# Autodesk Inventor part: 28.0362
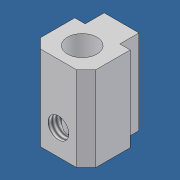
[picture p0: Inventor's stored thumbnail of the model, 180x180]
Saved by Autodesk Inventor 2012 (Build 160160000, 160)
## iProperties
Created: 2011-09
Part Number: 28.0362
Document SubType Name: Modeling
Designer: Administrator
Density: 2.71 g/cm^3
Material: Aluminum-6061
Mass: 6.60718 g
Surface Area: 18.2138 cm^2
Volume: 2.43808 cm^3
Description: CLAMP BLOCK
Vendor: S
Author: Administrator
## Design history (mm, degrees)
sketch "Sketch1"
  geometry: L1 (-4.1, 9.295)-(4.1, 9.295); L2 (-4.1, 9.295)-(-4.1, 4.795); L3 (4.1, 9.295)-(4.1, 4.795); L4 (4.1, 4.795)-(6.55, 4.795); L5 (6.55, 4.795)-(6.55, -5.615); L6 (6.55, -5.615)-(-6.55, -5.615); L7 (-6.55, -5.615)-(-6.55, 4.795); L8 (-6.55, 4.795)-(-4.1, 4.795); C1 r 3.485 at (0, 0); 2 further points
  constraints: 16 end point, 4 parallel, 2 collinear, 2 perpendicular, 1 centre point, 1 coincident, 1 horizontal, 1 horizontal alignment, 1 midpoint, 1 vertical alignment
  dimensions: "d0" = 6.97 diameter of C1; "d1" = 8.2 distance of L1.start L1.end; "d2" = 13.1 distance between parallel lines of L5 L7; "d3" = 14.91 distance between parallel lines of L6 L1; "d4" = 4.5 distance of L1.start L2.end; "d5" = 2.13 distance edge to line of C1 L6
extrude "Extrusion1" new body sketch "Sketch1" stored distance "d7" = 20; taper "d8" = 0 deg
chamfer "Chamfer1" distance "d9" = 2.3; stored, may be unused: second distance "d10" = 2, angle "d11" = 45 deg
sketch "Sketch2"
  geometry: L1 (8.2, 20)-(0, 20) reference; 3 further points
  constraints: 2 vertical alignment, 1 midpoint
  dimensions: "d12" = 6 distance from line of point (4.1, 14) L1
hole "Hole1" sketch "Sketch2" at (4.1, 14) diameter "d13" = 4.917; stored, may be unused: countersink angle "d17" = 90 deg, drill point angle "d19" = 118 deg; dims "d14" = 6, "d15" = 4, "d16" = 2, "d18" = 8
body "Solid1"
